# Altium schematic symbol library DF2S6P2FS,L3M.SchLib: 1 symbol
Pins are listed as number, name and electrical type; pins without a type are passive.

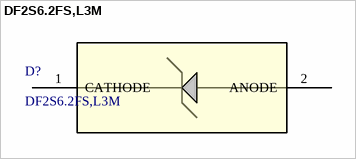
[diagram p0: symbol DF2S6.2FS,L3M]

## DF2S6.2FS,L3M
designator D?
Unidirectional TVS Diode (ESD Protection Diode), 5.0 V, SOD-923; Manufacturer_Name: Toshiba Electronic Devices & Storage Corp.
footprint SOD-923_TOS
pins: 1 CATHODE, 2 ANODE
